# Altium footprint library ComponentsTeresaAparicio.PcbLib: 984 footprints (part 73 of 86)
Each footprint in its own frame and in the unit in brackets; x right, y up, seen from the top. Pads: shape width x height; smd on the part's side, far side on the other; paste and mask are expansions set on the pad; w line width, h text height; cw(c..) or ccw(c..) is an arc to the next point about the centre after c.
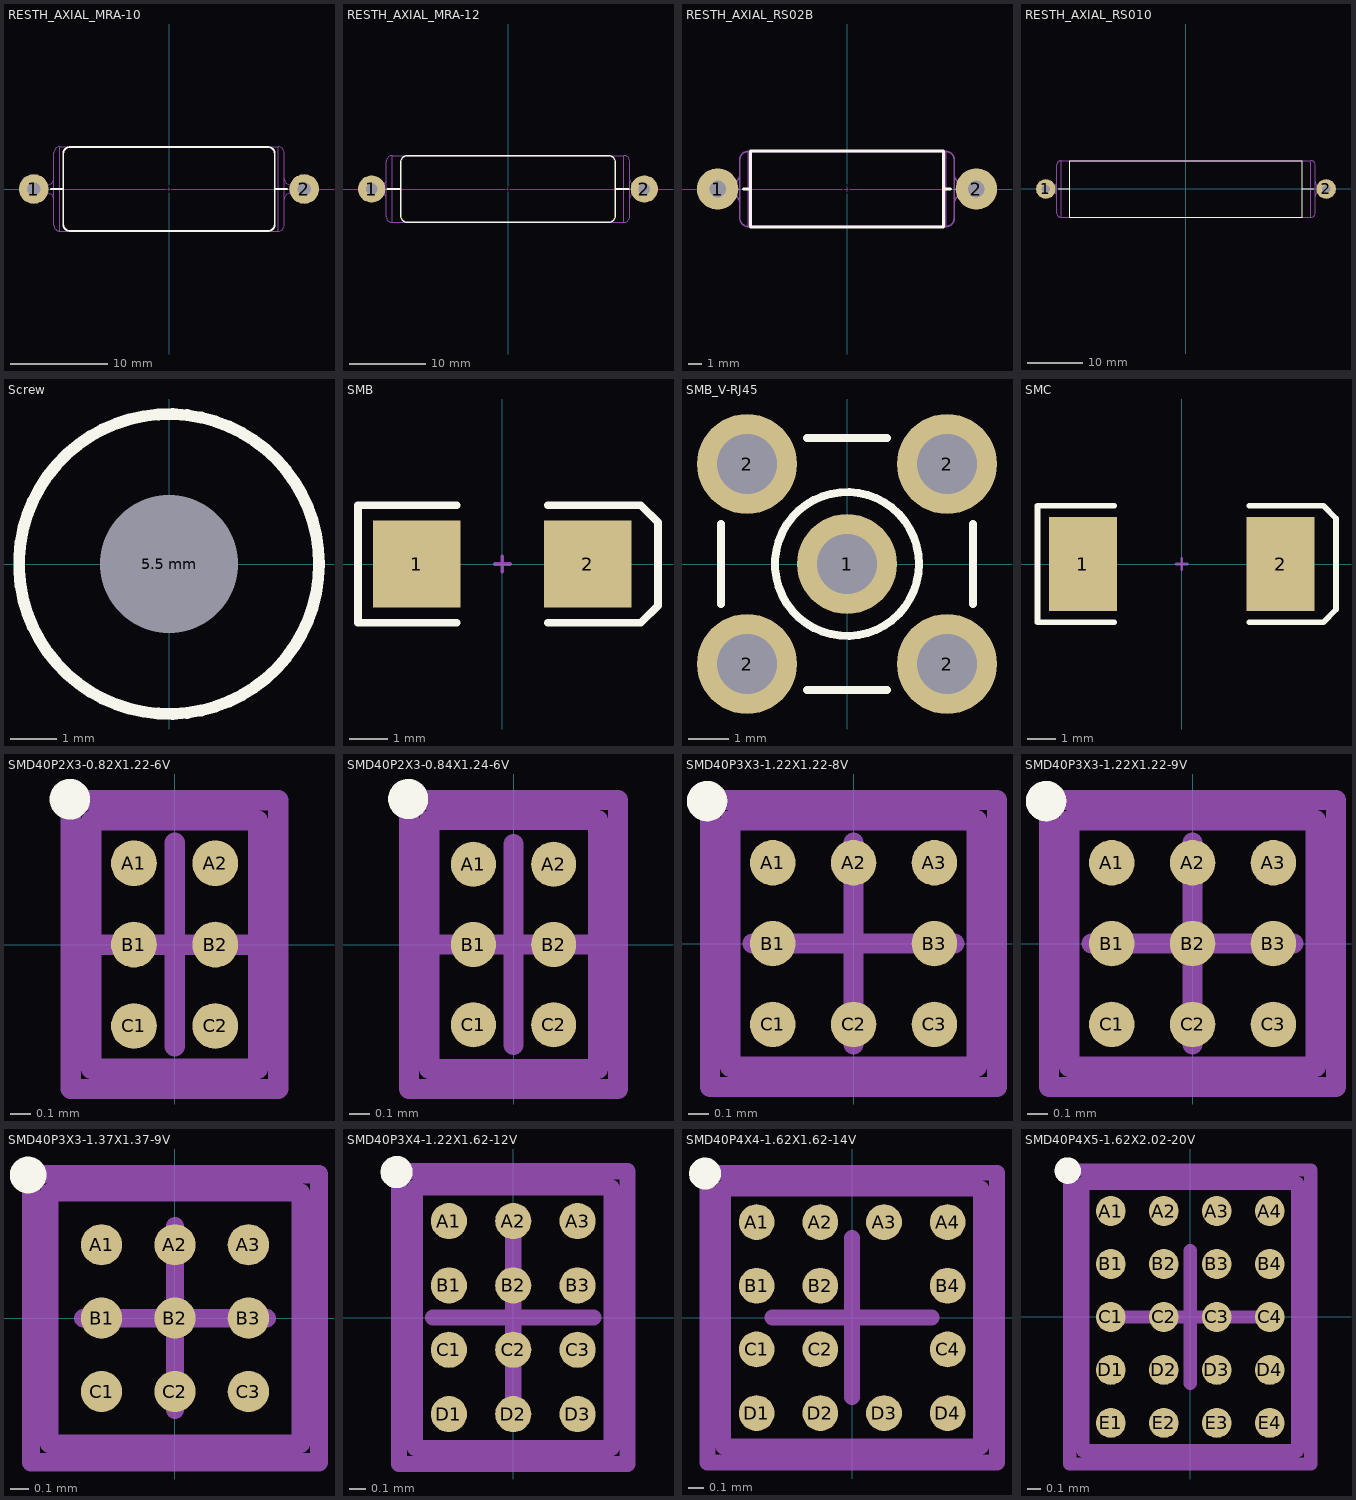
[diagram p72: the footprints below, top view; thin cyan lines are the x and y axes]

## RESTH_AXIAL_MRA-10 [mil] "MRA-10 Axial Resistor Thru-Hole; 2 Leads"
height 343
pads (3):
  round 50 on Mech14: 0(0,0)
  round 120 hole 54: 1(-550,0) 2(550,0)
Top Overlay:
  lines w7.87: -480,0 -430,0 ; 430,0 480,0 ; -430,-145 ccw(c-405,-145) -405,-170 405,-170 ccw(c405,-145) 430,-145 430,145 ccw(c405,145) 405,170 -405,170 ccw(c-405,145) -430,145 -430,-145
Mechanical 13:
  lines w5: -516,-17 -516,17 ; -493.5,-16.89 -493.5,17 ; -468.5,-42 ccw(c-493.5,-42) -493.5,-17 -550,-17 cw(c-550,0) -550,17 -493.5,17 ; -468.5,42 cw(c-493.5,42) -493.5,17 ; 468.5,-42 cw(c493.5,-42) 493.5,-17 ; 468.5,42 ccw(c493.5,42) 493.5,17 550,17 cw(c550,0) 550,-17 493.5,-17 ; 493.5,16.89 493.5,-17 ; 516,-17 516,17 ; -443.5,-171.5 cw(c-443.5,-146.5) -468.5,-146.5 -468.5,146.5 cw(c-443.5,146.5) -443.5,171.5 ; -443.5,-171.5 -443.5,171.5 ; -443.5,-171.5 443.5,-171.5 ; -443.5,171.5 443.5,171.5 ; 443.5,-171.5 ccw(c443.5,-146.5) 468.5,-146.5 468.5,146.5 ccw(c443.5,146.5) 443.5,171.5 ; 443.5,-171.5 443.5,171.5
3D body: height 341.65, standoff -100, extent -566.99,-171.16 567,171.17

## RESTH_AXIAL_MRA-12 [mil] "MRA-12 Axial Resistor Thru-Hole; 2 Leads"
height 343
pads (3):
  round 50 on Mech14: 0(0,0)
  round 140 hole 60: 1(-700,0) 2(700,0)
Top Overlay:
  lines w7.87: -620,0 -550,0 ; 550,0 620,0 ; -550,-139.99 ccw(c-520,-139.99) -520,-169.99 520,-170 ccw(c519.99,-139.99) 549.99,-139.99 550,140 ccw(c519.99,140) 519.99,170 -520,170 ccw(c-520,140) -550,140 -550,-140
Mechanical 13:
  lines w5: -666,-17 -666,17 ; -625,-47 ccw(c-655,-47) -655,-17 ; -625,47 cw(c-655,47) -655,17 ; 625,-47 cw(c655,-47) 655,-17 ; 625,47 ccw(c655,47) 655,17 ; 666,-17 666,17 ; -655,-17 -655,17 ; -655,-17 -700,-17 cw(c-700,0) -700,17 -655,17 ; -595,-171.5 cw(c-595,-141.5) -625,-141.5 -625,141.5 cw(c-595,141.5) -595,171.5 ; -595,-171.5 -595,171.5 ; -595,-171.5 595,-171.5 ; -595,171.5 595,171.5 ; 595,-171.5 ccw(c595,-141.5) 625,-141.5 625,141.5 ccw(c595,141.5) 595,171.5 ; 595,-171.5 595,171.5 ; 655,-17 655,17 ; 655,-17 700,-17 ccw(c700,0) 700,17 655,17
3D body: height 341.65, standoff -100, extent -717,-171.15 717,171.17

## RESTH_AXIAL_RS02B [mil] "Axial Resistor Thru-Hole; 2 Leads"
height 218
pads (3):
  round 50 on Mech14: 0(0,0)
  round 120 hole 48: 1(-375,0) 2(375,0)
Top Overlay:
  lines w7.87: -300,0 -280,0 ; 280,0 300,0 ; -280,-110 280,-110 280,110 -280,110 -280,-110
Mechanical 13:
  lines w5: -341,-17 -341,17 ; -311,-42 ccw(c-336,-42) -336,-17 ; -311,42 cw(c-336,42) -336,17 ; 311,-42 cw(c336,-42) 336,-17 ; 311,42 ccw(c336,42) 336,17 ; 341,-17 341,17 ; -336,-17 -336,17 ; -336,-17 -375,-17 cw(c-375,0) -375,17 -336,17 ; -286,-109 cw(c-286,-84) -311,-84 -311,84 cw(c-286,84) -286,109 ; -286,-109 -286,109 ; -286,-109 286,-109 ; -286,109 286,109 ; 286,-109 ccw(c286,-84) 311,-84 311,84 ccw(c286,84) 286,109 ; 286,-109 286,109 ; 336,-17 336,17 ; 336,-17 375,-17 ccw(c375,0) 375,17 336,17
3D body: height 217.14, standoff -100, extent -392,-108.78 392,108.79

## RESTH_AXIAL_RS010 [mil] "Axial Resistor Thru-Hole; 2 Leads"
height 406
pads (3):
  round 50 on Mech14: 0(0,0)
  round 140 hole 60: 1(-1000,0) 2(1000,0)
Top Overlay:
  lines w7.87: -910,0 -830,0 ; 830,0 910,0 ; -830,-200 -830,200 830,200 830,-200 -830,-200
Mechanical 13:
  lines w5: -958,-21 -958,21 ; -921,-51 ccw(c-951,-51) -951,-21 ; -921,51 cw(c-951,51) -951,21 ; 921,-51 cw(c951,-51) 951,-21 ; 921,51 ccw(c951,51) 951,21 ; 958,-21 958,21 ; -951,-21 -1000,-21 cw(c-1000,0) -1000,21 -951,21 ; -951,-21 -951,21 ; -891,-203 cw(c-891,-173) -921,-173 -921,173 cw(c-891,173) -891,203 ; -891,-203 891,-203 ; -891,-203 -891,203 ; -891,203 891,203 ; 891,-203 ccw(c891,-173) 921,-173 921,173 ccw(c891,173) 891,203 ; 891,-203 891,203 ; 951,-21 1000,-21 ccw(c1000,0) 1000,21 951,21 ; 951,-21 951,21
3D body: height 404.4, standoff -100, extent -1020.99,-202.59 1021,202.61

## Screw [mil]
pads (1):
  round 60 hole 118.11: "5.5 mm"(0,0)
Top Overlay:
  circle w10: c0,0 r128.06
3D body: height 318.11, standoff -429.92, extent -110,-110 106.54,106.54

## SMB [mm] "DO-214-AA/SMB; 2 C-Bend Leads; Body 5.3 x 3.6 mm, inc. leads (LxW)"
height 2.54
pads (2):
  rect 2.3x2.3 smd: 1(-2.25,0) 2(2.25,0)
Top Overlay:
  lines w0.2: -1.2,-1.55 -3.8,-1.55 -3.8,1.55 -1.2,1.55 ; 1.2,-1.55 3.65,-1.55 4.1,-1.1 4.1,1.1 3.65,1.55 1.2,1.55
Mechanical 1:
  lines w0.1: -0.2,0 0.2,0 ; 0,-0.2 0,0.2

## SMB_V-RJ45 [mm] "Connector; SMB Straight"
pads (5):
  round 2.5 hole 1.5: 1(0,0) 2(-2.5,-2.5) 2(-2.5,2.5) 2(2.5,-2.5) 2(2.5,2.5)
Top Overlay:
  circle w0.2: c0,0 r1.8
  lines w0.2: -3.15,-1 -3.15,1 ; -1,-3.15 1,-3.15 ; -1,3.15 1,3.15 ; 3.15,-1 3.15,1
Mechanical 1:
  circle w0.025: c0,0 r0.2
  circle w0.025: c0,0 r1.05
  circle w0.025: c0,0 r1.8

## SMC [mm] "DO-214-AB/SMC; 2 C-Bend Leads; Body 7.9 x 5.9 mm, inc. leads (LxW)"
height 2.65
pads (2):
  rect 2.4x3.3 smd: 1(-3.475,0) 2(3.475,0)
Top Overlay:
  lines w0.2: -2.375,-2.05 -5.075,-2.05 -5.075,2.05 -2.375,2.05 ; 2.375,-2.05 4.975,-2.05 5.425,-1.6 5.425,1.6 4.975,2.055 ; 2.375,2.05 4.975,2.05
Mechanical 1:
  lines w0.1: -0.2,0 0.2,0 ; 0,-0.2 0,0.2

## SMD40P2X3-0.82X1.22-6V [mm] "Micro SMD, 6-Leads, Body 1.22x0.82mm, Pitch 0.4mm, NSC Recommended"
height 0.68
pads (6):
  round 0.225 smd paste-0.112 mask+0.05: A1(-0.2,0.4) A2(0.2,0.4) B1(-0.2,0) B2(0.2,0) C1(-0.2,-0.4) C2(0.2,-0.4)
Top Overlay:
  circle w0.1: c-0.515,0.715 r0.05
Top Paste:
  circle w0.05: c0.3,-0.5 r0.025
  circle w0.05: c0.15,-0.35 r0.025
  circle w0.05: c0.15,-0.5 r0.025
  circle w0.05: c0.3,-0.35 r0.025
  circle w0.05: c-0.15,-0.5 r0.025
  circle w0.05: c-0.3,-0.35 r0.025
  circle w0.05: c-0.3,-0.5 r0.025
  circle w0.05: c-0.15,-0.35 r0.025
  circle w0.05: c0.3,-0.075 r0.025
  circle w0.05: c0.15,0.075 r0.025
  circle w0.05: c0.15,-0.075 r0.025
  circle w0.05: c0.3,0.075 r0.025
  circle w0.05: c-0.15,-0.075 r0.025
  circle w0.05: c-0.3,0.075 r0.025
  circle w0.05: c-0.3,-0.075 r0.025
  circle w0.05: c-0.15,0.075 r0.025
  circle w0.05: c0.3,0.35 r0.025
  circle w0.05: c0.15,0.5 r0.025
  circle w0.05: c0.15,0.35 r0.025
  circle w0.05: c0.3,0.5 r0.025
  circle w0.05: c-0.15,0.35 r0.025
  circle w0.05: c-0.3,0.5 r0.025
  circle w0.05: c-0.3,0.35 r0.025
  circle w0.05: c-0.15,0.5 r0.025
  region: 0.15,-0.35 0.15,-0.5 0.3,-0.5 0.3,-0.35
  region: 0.35,-0.5 0.35,-0.35 0.3,-0.35 0.3,-0.5
  region: 0.3,-0.3 0.15,-0.3 0.15,-0.35 0.3,-0.35
  region: 0.1,-0.35 0.1,-0.5 0.15,-0.5 0.15,-0.35
  rectangle: 0.15,-0.55 0.3,-0.5
  region: -0.3,-0.35 -0.3,-0.5 -0.15,-0.5 -0.15,-0.35
  region: -0.1,-0.5 -0.1,-0.35 -0.15,-0.35 -0.15,-0.5
  region: -0.15,-0.3 -0.3,-0.3 -0.3,-0.35 -0.15,-0.35
  region: -0.35,-0.35 -0.35,-0.5 -0.3,-0.5 -0.3,-0.35
  rectangle: -0.3,-0.55 -0.15,-0.5
  region: 0.15,0.075 0.15,-0.075 0.3,-0.075 0.3,0.075
  region: 0.35,-0.075 0.35,0.075 0.3,0.075 0.3,-0.075
  region: 0.3,0.125 0.15,0.125 0.15,0.075 0.3,0.075
  region: 0.1,0.075 0.1,-0.075 0.15,-0.075 0.15,0.075
  rectangle: 0.15,-0.125 0.3,-0.075
  region: -0.3,0.075 -0.3,-0.075 -0.15,-0.075 -0.15,0.075
  region: -0.1,-0.075 -0.1,0.075 -0.15,0.075 -0.15,-0.075
  region: -0.15,0.125 -0.3,0.125 -0.3,0.075 -0.15,0.075
  region: -0.35,0.075 -0.35,-0.075 -0.3,-0.075 -0.3,0.075
  rectangle: -0.3,-0.125 -0.15,-0.075
  region: 0.15,0.5 0.15,0.35 0.3,0.35 0.3,0.5
  region: 0.35,0.35 0.35,0.5 0.3,0.5 0.3,0.35
  region: 0.3,0.55 0.15,0.55 0.15,0.5 0.3,0.5
  region: 0.1,0.5 0.1,0.35 0.15,0.35 0.15,0.5
  rectangle: 0.15,0.3 0.3,0.35
  region: -0.3,0.5 -0.3,0.35 -0.15,0.35 -0.15,0.5
  region: -0.1,0.35 -0.1,0.5 -0.15,0.5 -0.15,0.35
  region: -0.15,0.55 -0.3,0.55 -0.3,0.5 -0.15,0.5
  region: -0.35,0.5 -0.35,0.35 -0.3,0.35 -0.3,0.5
  rectangle: -0.3,0.3 -0.15,0.35
Mechanical 13:
  lines w0.1: -0.41,-0.61 0.41,-0.61 0.41,0.61 -0.41,0.61 -0.41,-0.61
Mechanical 15:
  lines w0.1: -0.5,0 0.5,0 ; 0,-0.5 0,0.5 ; -0.51,-0.71 0.51,-0.71 0.51,0.71 -0.51,0.71 -0.51,-0.71
3D body: height 0.68, standoff 0, extent -0.41,-0.61 0.41,0.61

## SMD40P2X3-0.84X1.24-6V [mm] "Micro SMD, 6-Leads, Body 1.24x0.84mm, Pitch 0.4mm, NSC Recommended"
height 0.68
pads (6):
  round 0.225 smd paste-0.112 mask+0.05: A1(-0.2,0.4) A2(0.2,0.4) B1(-0.2,0) B2(0.2,0) C1(-0.2,-0.4) C2(0.2,-0.4)
Top Overlay:
  circle w0.1: c-0.525,0.725 r0.05
Top Paste:
  circle w0.05: c0.15,0.075 r0.025
  circle w0.05: c0.3,-0.075 r0.025
  circle w0.05: c0.15,-0.075 r0.025
  circle w0.05: c0.3,0.075 r0.025
  circle w0.05: c0.15,0.35 r0.025
  circle w0.05: c0.3,0.5 r0.025
  circle w0.05: c0.3,0.35 r0.025
  circle w0.05: c0.15,0.5 r0.025
  circle w0.05: c0.15,-0.35 r0.025
  circle w0.05: c0.3,-0.5 r0.025
  circle w0.05: c0.3,-0.35 r0.025
  circle w0.05: c0.15,-0.5 r0.025
  circle w0.05: c-0.15,0.075 r0.025
  circle w0.05: c-0.3,-0.075 r0.025
  circle w0.05: c-0.15,-0.075 r0.025
  circle w0.05: c-0.3,0.075 r0.025
  circle w0.05: c-0.15,0.35 r0.025
  circle w0.05: c-0.3,0.5 r0.025
  circle w0.05: c-0.3,0.35 r0.025
  circle w0.05: c-0.15,0.5 r0.025
  circle w0.05: c-0.15,-0.35 r0.025
  circle w0.05: c-0.3,-0.5 r0.025
  circle w0.05: c-0.3,-0.35 r0.025
  circle w0.05: c-0.15,-0.5 r0.025
  region: 0.3,0.075 0.15,0.075 0.15,-0.075 0.3,-0.075
  rectangle: 0.15,0.075 0.3,0.125
  region: 0.3,0.075 0.3,-0.075 0.35,-0.075 0.35,0.075
  region: 0.3,-0.075 0.15,-0.075 0.15,-0.125 0.3,-0.125
  region: 0.15,-0.075 0.15,0.075 0.1,0.075 0.1,-0.075
  region: 0.15,0.5 0.15,0.35 0.3,0.35 0.3,0.5
  region: 0.15,0.35 0.15,0.5 0.1,0.5 0.1,0.35
  rectangle: 0.15,0.5 0.3,0.55
  region: 0.3,0.5 0.3,0.35 0.35,0.35 0.35,0.5
  region: 0.3,0.35 0.15,0.35 0.15,0.3 0.3,0.3
  region: 0.3,-0.5 0.3,-0.35 0.15,-0.35 0.15,-0.5
  region: 0.1,-0.35 0.1,-0.5 0.15,-0.5 0.15,-0.35
  rectangle: 0.15,-0.55 0.3,-0.5
  region: 0.35,-0.5 0.35,-0.35 0.3,-0.35 0.3,-0.5
  region: 0.3,-0.3 0.15,-0.3 0.15,-0.35 0.3,-0.35
  rectangle: -0.3,-0.075 -0.15,0.075
  region: -0.15,0.125 -0.3,0.125 -0.3,0.075 -0.15,0.075
  region: -0.35,0.075 -0.35,-0.075 -0.3,-0.075 -0.3,0.075
  rectangle: -0.3,-0.125 -0.15,-0.075
  region: -0.1,-0.075 -0.1,0.075 -0.15,0.075 -0.15,-0.075
  region: -0.3,0.5 -0.3,0.35 -0.15,0.35 -0.15,0.5
  region: -0.1,0.35 -0.1,0.5 -0.15,0.5 -0.15,0.35
  region: -0.15,0.55 -0.3,0.55 -0.3,0.5 -0.15,0.5
  region: -0.35,0.5 -0.35,0.35 -0.3,0.35 -0.3,0.5
  rectangle: -0.3,0.3 -0.15,0.35
  region: -0.15,-0.5 -0.15,-0.35 -0.3,-0.35 -0.3,-0.5
  region: -0.15,-0.35 -0.15,-0.5 -0.1,-0.5 -0.1,-0.35
  region: -0.15,-0.5 -0.3,-0.5 -0.3,-0.55 -0.15,-0.55
  region: -0.3,-0.5 -0.3,-0.35 -0.35,-0.35 -0.35,-0.5
  rectangle: -0.3,-0.35 -0.15,-0.3
Mechanical 13:
  lines w0.1: -0.42,-0.62 0.42,-0.62 0.42,0.62 -0.42,0.62 -0.42,-0.62
Mechanical 15:
  lines w0.1: -0.5,0 0.5,0 ; 0,-0.5 0,0.5 ; -0.52,-0.72 0.52,-0.72 0.52,0.72 -0.52,0.72 -0.52,-0.72
3D body: height 0.68, standoff 0.17, extent -0.419,-0.619 0.419,0.619

## SMD40P3X3-1.22X1.22-8V [mm] "Micro SMD, 8-Leads, Body 1.22x1.22mm, Pitch 0.4mm, NSC Recommended"
height 0.68
pads (8):
  round 0.225 smd paste-0.112 mask+0.05: A1(-0.4,0.4) A2(0,0.4) A3(0.4,0.4) B1(-0.4,0) B3(0.4,0) C1(-0.4,-0.4) C2(0,-0.4) C3(0.4,-0.4)
Top Overlay:
  circle w0.1: c-0.725,0.705 r0.05
Top Paste:
  circle w0.05: c0.35,-0.075 r0.025
  circle w0.05: c0.5,0.075 r0.025
  circle w0.05: c0.35,0.075 r0.025
  circle w0.05: c0.5,-0.075 r0.025
  circle w0.05: c-0.075,-0.35 r0.025
  circle w0.05: c0.075,-0.5 r0.025
  circle w0.05: c0.075,-0.35 r0.025
  circle w0.05: c-0.075,-0.5 r0.025
  circle w0.05: c-0.35,0.075 r0.025
  circle w0.05: c-0.5,-0.075 r0.025
  circle w0.05: c-0.35,-0.075 r0.025
  circle w0.05: c-0.5,0.075 r0.025
  circle w0.05: c0.075,0.35 r0.025
  circle w0.05: c-0.075,0.5 r0.025
  circle w0.05: c-0.075,0.35 r0.025
  circle w0.05: c0.075,0.5 r0.025
  circle w0.05: c-0.35,0.35 r0.025
  circle w0.05: c-0.5,0.5 r0.025
  circle w0.05: c-0.5,0.35 r0.025
  circle w0.05: c-0.35,0.5 r0.025
  circle w0.05: c0.35,0.35 r0.025
  circle w0.05: c0.5,0.5 r0.025
  circle w0.05: c0.5,0.35 r0.025
  circle w0.05: c0.35,0.5 r0.025
  circle w0.05: c0.35,-0.35 r0.025
  circle w0.05: c0.5,-0.5 r0.025
  circle w0.05: c0.5,-0.35 r0.025
  circle w0.05: c0.35,-0.5 r0.025
  circle w0.05: c-0.35,-0.35 r0.025
  circle w0.05: c-0.5,-0.5 r0.025
  circle w0.05: c-0.5,-0.35 r0.025
  circle w0.05: c-0.35,-0.5 r0.025
  region: 0.5,0.075 0.35,0.075 0.35,-0.075 0.5,-0.075
  rectangle: 0.35,-0.125 0.5,-0.075
  region: 0.55,-0.075 0.55,0.075 0.5,0.075 0.5,-0.075
  region: 0.5,0.125 0.35,0.125 0.35,0.075 0.5,0.075
  region: 0.3,0.075 0.3,-0.075 0.35,-0.075 0.35,0.075
  region: 0.075,-0.5 0.075,-0.35 -0.075,-0.35 -0.075,-0.5
  region: -0.125,-0.35 -0.125,-0.5 -0.075,-0.5 -0.075,-0.35
  rectangle: -0.075,-0.55 0.075,-0.5
  region: 0.125,-0.5 0.125,-0.35 0.075,-0.35 0.075,-0.5
  region: 0.075,-0.3 -0.075,-0.3 -0.075,-0.35 0.075,-0.35
  rectangle: -0.5,-0.075 -0.35,0.075
  region: -0.35,0.125 -0.5,0.125 -0.5,0.075 -0.35,0.075
  region: -0.55,0.075 -0.55,-0.075 -0.5,-0.075 -0.5,0.075
  rectangle: -0.5,-0.125 -0.35,-0.075
  region: -0.3,-0.075 -0.3,0.075 -0.35,0.075 -0.35,-0.075
  region: -0.075,0.5 -0.075,0.35 0.075,0.35 0.075,0.5
  region: 0.125,0.35 0.125,0.5 0.075,0.5 0.075,0.35
  region: 0.075,0.55 -0.075,0.55 -0.075,0.5 0.075,0.5
  region: -0.125,0.5 -0.125,0.35 -0.075,0.35 -0.075,0.5
  rectangle: -0.075,0.3 0.075,0.35
  region: -0.5,0.5 -0.5,0.35 -0.35,0.35 -0.35,0.5
  region: -0.3,0.35 -0.3,0.5 -0.35,0.5 -0.35,0.35
  region: -0.35,0.55 -0.5,0.55 -0.5,0.5 -0.35,0.5
  region: -0.55,0.5 -0.55,0.35 -0.5,0.35 -0.5,0.5
  rectangle: -0.5,0.3 -0.35,0.35
  region: 0.35,0.5 0.35,0.35 0.5,0.35 0.5,0.5
  region: 0.35,0.35 0.35,0.5 0.3,0.5 0.3,0.35
  rectangle: 0.35,0.5 0.5,0.55
  region: 0.5,0.5 0.5,0.35 0.55,0.35 0.55,0.5
  region: 0.5,0.35 0.35,0.35 0.35,0.3 0.5,0.3
  region: 0.5,-0.5 0.5,-0.35 0.35,-0.35 0.35,-0.5
  region: 0.3,-0.35 0.3,-0.5 0.35,-0.5 0.35,-0.35
  rectangle: 0.35,-0.55 0.5,-0.5
  region: 0.55,-0.5 0.55,-0.35 0.5,-0.35 0.5,-0.5
  region: 0.5,-0.3 0.35,-0.3 0.35,-0.35 0.5,-0.35
  region: -0.35,-0.5 -0.35,-0.35 -0.5,-0.35 -0.5,-0.5
  region: -0.35,-0.35 -0.35,-0.5 -0.3,-0.5 -0.3,-0.35
  region: -0.35,-0.5 -0.5,-0.5 -0.5,-0.55 -0.35,-0.55
  region: -0.5,-0.5 -0.5,-0.35 -0.55,-0.35 -0.55,-0.5
  rectangle: -0.5,-0.35 -0.35,-0.3
Mechanical 13:
  lines w0.1: -0.61,-0.61 0.61,-0.61 0.61,0.61 -0.61,0.61 -0.61,-0.61
Mechanical 15:
  lines w0.1: -0.5,0 0.5,0 ; 0,-0.5 0,0.5 ; -0.71,-0.71 0.71,-0.71 0.71,0.71 -0.71,0.71 -0.71,-0.71
3D body: height 0.68, standoff 0.17, extent -0.609,-0.609 0.609,0.609

## SMD40P3X3-1.22X1.22-9V [mm] "Micro SMD, 9-Leads, Body 1.22x1.22mm, Pitch 0.4mm, NSC Recommended"
height 0.68
pads (9):
  round 0.225 smd paste-0.112 mask+0.05: A1(-0.4,0.4) A2(0,0.4) A3(0.4,0.4) B1(-0.4,0) B2(0,0) B3(0.4,0) C1(-0.4,-0.4) C2(0,-0.4) C3(0.4,-0.4)
Top Overlay:
  circle w0.1: c-0.725,0.705 r0.05
Top Paste:
  circle w0.05: c0.075,-0.075 r0.025
  circle w0.05: c-0.075,0.075 r0.025
  circle w0.05: c-0.075,-0.075 r0.025
  circle w0.05: c0.075,0.075 r0.025
  circle w0.05: c-0.35,-0.5 r0.025
  circle w0.05: c-0.5,-0.35 r0.025
  circle w0.05: c-0.5,-0.5 r0.025
  circle w0.05: c-0.35,-0.35 r0.025
  circle w0.05: c0.35,-0.5 r0.025
  circle w0.05: c0.5,-0.35 r0.025
  circle w0.05: c0.5,-0.5 r0.025
  circle w0.05: c0.35,-0.35 r0.025
  circle w0.05: c0.35,0.5 r0.025
  circle w0.05: c0.5,0.35 r0.025
  circle w0.05: c0.5,0.5 r0.025
  circle w0.05: c0.35,0.35 r0.025
  circle w0.05: c-0.35,0.5 r0.025
  circle w0.05: c-0.5,0.35 r0.025
  circle w0.05: c-0.5,0.5 r0.025
  circle w0.05: c-0.35,0.35 r0.025
  circle w0.05: c0.075,0.5 r0.025
  circle w0.05: c-0.075,0.35 r0.025
  circle w0.05: c-0.075,0.5 r0.025
  circle w0.05: c0.075,0.35 r0.025
  circle w0.05: c-0.5,0.075 r0.025
  circle w0.05: c-0.35,-0.075 r0.025
  circle w0.05: c-0.5,-0.075 r0.025
  circle w0.05: c-0.35,0.075 r0.025
  circle w0.05: c-0.075,-0.5 r0.025
  circle w0.05: c0.075,-0.35 r0.025
  circle w0.05: c0.075,-0.5 r0.025
  circle w0.05: c-0.075,-0.35 r0.025
  circle w0.05: c0.5,-0.075 r0.025
  circle w0.05: c0.35,0.075 r0.025
  circle w0.05: c0.5,0.075 r0.025
  circle w0.05: c0.35,-0.075 r0.025
  region: -0.075,0.075 -0.075,-0.075 0.075,-0.075 0.075,0.075
  region: 0.125,-0.075 0.125,0.075 0.075,0.075 0.075,-0.075
  region: 0.075,0.125 -0.075,0.125 -0.075,0.075 0.075,0.075
  region: -0.125,0.075 -0.125,-0.075 -0.075,-0.075 -0.075,0.075
  rectangle: -0.075,-0.125 0.075,-0.075
  rectangle: -0.5,-0.35 -0.35,-0.3
  region: -0.5,-0.5 -0.5,-0.35 -0.55,-0.35 -0.55,-0.5
  region: -0.35,-0.5 -0.5,-0.5 -0.5,-0.55 -0.35,-0.55
  region: -0.35,-0.35 -0.35,-0.5 -0.3,-0.5 -0.3,-0.35
  region: -0.35,-0.5 -0.35,-0.35 -0.5,-0.35 -0.5,-0.5
  region: 0.5,-0.3 0.35,-0.3 0.35,-0.35 0.5,-0.35
  region: 0.55,-0.5 0.55,-0.35 0.5,-0.35 0.5,-0.5
  rectangle: 0.35,-0.55 0.5,-0.5
  region: 0.3,-0.35 0.3,-0.5 0.35,-0.5 0.35,-0.35
  region: 0.5,-0.5 0.5,-0.35 0.35,-0.35 0.35,-0.5
  region: 0.5,0.35 0.35,0.35 0.35,0.3 0.5,0.3
  region: 0.5,0.5 0.5,0.35 0.55,0.35 0.55,0.5
  rectangle: 0.35,0.5 0.5,0.55
  region: 0.35,0.35 0.35,0.5 0.3,0.5 0.3,0.35
  region: 0.35,0.5 0.35,0.35 0.5,0.35 0.5,0.5
  rectangle: -0.5,0.3 -0.35,0.35
  region: -0.55,0.5 -0.55,0.35 -0.5,0.35 -0.5,0.5
  region: -0.35,0.55 -0.5,0.55 -0.5,0.5 -0.35,0.5
  region: -0.3,0.35 -0.3,0.5 -0.35,0.5 -0.35,0.35
  region: -0.5,0.5 -0.5,0.35 -0.35,0.35 -0.35,0.5
  rectangle: -0.075,0.3 0.075,0.35
  region: -0.125,0.5 -0.125,0.35 -0.075,0.35 -0.075,0.5
  region: 0.075,0.55 -0.075,0.55 -0.075,0.5 0.075,0.5
  region: 0.125,0.35 0.125,0.5 0.075,0.5 0.075,0.35
  region: -0.075,0.5 -0.075,0.35 0.075,0.35 0.075,0.5
  region: -0.3,-0.075 -0.3,0.075 -0.35,0.075 -0.35,-0.075
  rectangle: -0.5,-0.125 -0.35,-0.075
  region: -0.55,0.075 -0.55,-0.075 -0.5,-0.075 -0.5,0.075
  region: -0.35,0.125 -0.5,0.125 -0.5,0.075 -0.35,0.075
  rectangle: -0.5,-0.075 -0.35,0.075
  region: 0.075,-0.3 -0.075,-0.3 -0.075,-0.35 0.075,-0.35
  region: 0.125,-0.5 0.125,-0.35 0.075,-0.35 0.075,-0.5
  rectangle: -0.075,-0.55 0.075,-0.5
  region: -0.125,-0.35 -0.125,-0.5 -0.075,-0.5 -0.075,-0.35
  region: 0.075,-0.5 0.075,-0.35 -0.075,-0.35 -0.075,-0.5
  region: 0.3,0.075 0.3,-0.075 0.35,-0.075 0.35,0.075
  region: 0.5,0.125 0.35,0.125 0.35,0.075 0.5,0.075
  region: 0.55,-0.075 0.55,0.075 0.5,0.075 0.5,-0.075
  rectangle: 0.35,-0.125 0.5,-0.075
  region: 0.5,0.075 0.35,0.075 0.35,-0.075 0.5,-0.075
Mechanical 13:
  lines w0.1: -0.61,-0.61 0.61,-0.61 0.61,0.61 -0.61,0.61 -0.61,-0.61
Mechanical 15:
  lines w0.1: -0.5,0 0.5,0 ; 0,-0.5 0,0.5 ; -0.71,-0.71 0.71,-0.71 0.71,0.71 -0.71,0.71 -0.71,-0.71
3D body: height 0.68, standoff 0, extent -0.609,-0.609 0.609,0.609

## SMD40P3X3-1.37X1.37-9V [mm] "Micro SMD, 9-Leads, Body 1.37x1.37mm, Pitch 0.4mm, NSC Recommended"
height 0.68
pads (9):
  round 0.225 smd paste-0.112 mask+0.05: A1(-0.4,0.4) A2(0,0.4) A3(0.4,0.4) B1(-0.4,0) B2(0,0) B3(0.4,0) C1(-0.4,-0.4) C2(0,-0.4) C3(0.4,-0.4)
Top Overlay:
  circle w0.1: c-0.8,0.78 r0.05
Top Paste:
  circle w0.05: c-0.075,-0.35 r0.025
  circle w0.05: c0.075,-0.5 r0.025
  circle w0.05: c0.075,-0.35 r0.025
  circle w0.05: c-0.075,-0.5 r0.025
  circle w0.05: c-0.35,0.075 r0.025
  circle w0.05: c-0.5,-0.075 r0.025
  circle w0.05: c-0.35,-0.075 r0.025
  circle w0.05: c-0.5,0.075 r0.025
  circle w0.05: c0.075,0.35 r0.025
  circle w0.05: c-0.075,0.5 r0.025
  circle w0.05: c-0.075,0.35 r0.025
  circle w0.05: c0.075,0.5 r0.025
  circle w0.05: c0.35,-0.075 r0.025
  circle w0.05: c0.5,0.075 r0.025
  circle w0.05: c0.35,0.075 r0.025
  circle w0.05: c0.5,-0.075 r0.025
  circle w0.05: c-0.35,-0.5 r0.025
  circle w0.05: c-0.5,-0.35 r0.025
  circle w0.05: c-0.5,-0.5 r0.025
  circle w0.05: c-0.35,-0.35 r0.025
  circle w0.05: c0.35,-0.5 r0.025
  circle w0.05: c0.5,-0.35 r0.025
  circle w0.05: c0.5,-0.5 r0.025
  circle w0.05: c0.35,-0.35 r0.025
  circle w0.05: c0.35,0.5 r0.025
  circle w0.05: c0.5,0.35 r0.025
  circle w0.05: c0.5,0.5 r0.025
  circle w0.05: c0.35,0.35 r0.025
  circle w0.05: c-0.35,0.5 r0.025
  circle w0.05: c-0.5,0.35 r0.025
  circle w0.05: c-0.5,0.5 r0.025
  circle w0.05: c-0.35,0.35 r0.025
  circle w0.05: c0.075,0.075 r0.025
  circle w0.05: c-0.075,-0.075 r0.025
  circle w0.05: c-0.075,0.075 r0.025
  circle w0.05: c0.075,-0.075 r0.025
  region: 0.075,-0.5 0.075,-0.35 -0.075,-0.35 -0.075,-0.5
  region: -0.125,-0.35 -0.125,-0.5 -0.075,-0.5 -0.075,-0.35
  rectangle: -0.075,-0.55 0.075,-0.5
  region: 0.125,-0.5 0.125,-0.35 0.075,-0.35 0.075,-0.5
  region: 0.075,-0.3 -0.075,-0.3 -0.075,-0.35 0.075,-0.35
  rectangle: -0.5,-0.075 -0.35,0.075
  region: -0.35,0.125 -0.5,0.125 -0.5,0.075 -0.35,0.075
  region: -0.55,0.075 -0.55,-0.075 -0.5,-0.075 -0.5,0.075
  rectangle: -0.5,-0.125 -0.35,-0.075
  region: -0.3,-0.075 -0.3,0.075 -0.35,0.075 -0.35,-0.075
  region: -0.075,0.5 -0.075,0.35 0.075,0.35 0.075,0.5
  region: 0.125,0.35 0.125,0.5 0.075,0.5 0.075,0.35
  region: 0.075,0.55 -0.075,0.55 -0.075,0.5 0.075,0.5
  region: -0.125,0.5 -0.125,0.35 -0.075,0.35 -0.075,0.5
  rectangle: -0.075,0.3 0.075,0.35
  region: 0.5,0.075 0.35,0.075 0.35,-0.075 0.5,-0.075
  rectangle: 0.35,-0.125 0.5,-0.075
  region: 0.55,-0.075 0.55,0.075 0.5,0.075 0.5,-0.075
  region: 0.5,0.125 0.35,0.125 0.35,0.075 0.5,0.075
  region: 0.3,0.075 0.3,-0.075 0.35,-0.075 0.35,0.075
  rectangle: -0.5,-0.35 -0.35,-0.3
  region: -0.5,-0.5 -0.5,-0.35 -0.55,-0.35 -0.55,-0.5
  region: -0.35,-0.5 -0.5,-0.5 -0.5,-0.55 -0.35,-0.55
  region: -0.35,-0.35 -0.35,-0.5 -0.3,-0.5 -0.3,-0.35
  region: -0.35,-0.5 -0.35,-0.35 -0.5,-0.35 -0.5,-0.5
  region: 0.5,-0.3 0.35,-0.3 0.35,-0.35 0.5,-0.35
  region: 0.55,-0.5 0.55,-0.35 0.5,-0.35 0.5,-0.5
  rectangle: 0.35,-0.55 0.5,-0.5
  region: 0.3,-0.35 0.3,-0.5 0.35,-0.5 0.35,-0.35
  region: 0.5,-0.5 0.5,-0.35 0.35,-0.35 0.35,-0.5
  region: 0.5,0.35 0.35,0.35 0.35,0.3 0.5,0.3
  region: 0.5,0.5 0.5,0.35 0.55,0.35 0.55,0.5
  rectangle: 0.35,0.5 0.5,0.55
  region: 0.35,0.35 0.35,0.5 0.3,0.5 0.3,0.35
  region: 0.35,0.5 0.35,0.35 0.5,0.35 0.5,0.5
  rectangle: -0.5,0.3 -0.35,0.35
  region: -0.55,0.5 -0.55,0.35 -0.5,0.35 -0.5,0.5
  region: -0.35,0.55 -0.5,0.55 -0.5,0.5 -0.35,0.5
  region: -0.3,0.35 -0.3,0.5 -0.35,0.5 -0.35,0.35
  region: -0.5,0.5 -0.5,0.35 -0.35,0.35 -0.35,0.5
  rectangle: -0.075,-0.125 0.075,-0.075
  region: -0.125,0.075 -0.125,-0.075 -0.075,-0.075 -0.075,0.075
  region: 0.075,0.125 -0.075,0.125 -0.075,0.075 0.075,0.075
  region: 0.125,-0.075 0.125,0.075 0.075,0.075 0.075,-0.075
  region: -0.075,0.075 -0.075,-0.075 0.075,-0.075 0.075,0.075
Mechanical 13:
  lines w0.1: -0.685,-0.685 0.685,-0.685 0.685,0.685 -0.685,0.685 -0.685,-0.685
Mechanical 15:
  lines w0.1: -0.5,0 0.5,0 ; 0,-0.5 0,0.5 ; -0.785,-0.785 0.785,-0.785 0.785,0.785 -0.785,0.785 -0.785,-0.785
3D body: height 0.68, standoff 0, extent -0.684,-0.684 0.684,0.684

## SMD40P3X4-1.22X1.62-12V [mm] "Micro SMD, 12-Leads, Body 1.62x1.22mm, Pitch 0.4mm, NSC Recommended"
height 0.68
pads (12):
  round 0.225 smd paste-0.112 mask+0.05: A1(-0.4,0.6) A2(0,0.6) A3(0.4,0.6) B1(-0.4,0.2) B2(0,0.2) B3(0.4,0.2) C1(-0.4,-0.2) C2(0,-0.2) C3(0.4,-0.2) D1(-0.4,-0.6) D2(0,-0.6) D3(0.4,-0.6)
Top Overlay:
  circle w0.1: c-0.725,0.905 r0.05
Top Paste:
  circle w0.05: c0.075,-0.275 r0.025
  circle w0.05: c-0.075,-0.125 r0.025
  circle w0.05: c-0.075,-0.275 r0.025
  circle w0.05: c0.075,-0.125 r0.025
  circle w0.05: c0.075,0.125 r0.025
  circle w0.05: c-0.075,0.275 r0.025
  circle w0.05: c-0.075,0.125 r0.025
  circle w0.05: c0.075,0.275 r0.025
  circle w0.05: c-0.35,-0.125 r0.025
  circle w0.05: c-0.5,-0.275 r0.025
  circle w0.05: c-0.35,-0.275 r0.025
  circle w0.05: c-0.5,-0.125 r0.025
  circle w0.05: c-0.35,0.275 r0.025
  circle w0.05: c-0.5,0.125 r0.025
  circle w0.05: c-0.35,0.125 r0.025
  circle w0.05: c-0.5,0.275 r0.025
  circle w0.05: c0.075,0.55 r0.025
  circle w0.05: c-0.075,0.7 r0.025
  circle w0.05: c-0.075,0.55 r0.025
  circle w0.05: c0.075,0.7 r0.025
  circle w0.05: c0.35,0.125 r0.025
  circle w0.05: c0.5,0.275 r0.025
  circle w0.05: c0.35,0.275 r0.025
  circle w0.05: c0.5,0.125 r0.025
  circle w0.05: c0.35,-0.275 r0.025
  circle w0.05: c0.5,-0.125 r0.025
  circle w0.05: c0.35,-0.125 r0.025
  circle w0.05: c0.5,-0.275 r0.025
  circle w0.05: c-0.075,-0.55 r0.025
  circle w0.05: c0.075,-0.7 r0.025
  circle w0.05: c0.075,-0.55 r0.025
  circle w0.05: c-0.075,-0.7 r0.025
  circle w0.05: c-0.35,-0.55 r0.025
  circle w0.05: c-0.5,-0.7 r0.025
  circle w0.05: c-0.5,-0.55 r0.025
  circle w0.05: c-0.35,-0.7 r0.025
  circle w0.05: c-0.35,0.55 r0.025
  circle w0.05: c-0.5,0.7 r0.025
  circle w0.05: c-0.5,0.55 r0.025
  circle w0.05: c-0.35,0.7 r0.025
  circle w0.05: c0.35,0.55 r0.025
  circle w0.05: c0.5,0.7 r0.025
  circle w0.05: c0.5,0.55 r0.025
  circle w0.05: c0.35,0.7 r0.025
  circle w0.05: c0.35,-0.55 r0.025
  circle w0.05: c0.5,-0.7 r0.025
  circle w0.05: c0.5,-0.55 r0.025
  circle w0.05: c0.35,-0.7 r0.025
  region: -0.075,-0.125 -0.075,-0.275 0.075,-0.275 0.075,-0.125
  region: 0.125,-0.275 0.125,-0.125 0.075,-0.125 0.075,-0.275
  region: 0.075,-0.075 -0.075,-0.075 -0.075,-0.125 0.075,-0.125
  region: -0.125,-0.125 -0.125,-0.275 -0.075,-0.275 -0.075,-0.125
  rectangle: -0.075,-0.325 0.075,-0.275
  region: -0.075,0.275 -0.075,0.125 0.075,0.125 0.075,0.275
  region: 0.125,0.125 0.125,0.275 0.075,0.275 0.075,0.125
  region: 0.075,0.325 -0.075,0.325 -0.075,0.275 0.075,0.275
  region: -0.125,0.275 -0.125,0.125 -0.075,0.125 -0.075,0.275
  rectangle: -0.075,0.075 0.075,0.125
  rectangle: -0.5,-0.275 -0.35,-0.125
  region: -0.35,-0.075 -0.5,-0.075 -0.5,-0.125 -0.35,-0.125
  region: -0.55,-0.125 -0.55,-0.275 -0.5,-0.275 -0.5,-0.125
  rectangle: -0.5,-0.325 -0.35,-0.275
  region: -0.3,-0.275 -0.3,-0.125 -0.35,-0.125 -0.35,-0.275
  rectangle: -0.5,0.125 -0.35,0.275
  region: -0.35,0.325 -0.5,0.325 -0.5,0.275 -0.35,0.275
  region: -0.55,0.275 -0.55,0.125 -0.5,0.125 -0.5,0.275
  rectangle: -0.5,0.075 -0.35,0.125
  region: -0.3,0.125 -0.3,0.275 -0.35,0.275 -0.35,0.125
  region: -0.075,0.7 -0.075,0.55 0.075,0.55 0.075,0.7
  region: 0.125,0.55 0.125,0.7 0.075,0.7 0.075,0.55
  region: 0.075,0.75 -0.075,0.75 -0.075,0.7 0.075,0.7
  region: -0.125,0.7 -0.125,0.55 -0.075,0.55 -0.075,0.7
  rectangle: -0.075,0.5 0.075,0.55
  region: 0.5,0.275 0.35,0.275 0.35,0.125 0.5,0.125
  rectangle: 0.35,0.075 0.5,0.125
  region: 0.55,0.125 0.55,0.275 0.5,0.275 0.5,0.125
  region: 0.5,0.325 0.35,0.325 0.35,0.275 0.5,0.275
  region: 0.3,0.275 0.3,0.125 0.35,0.125 0.35,0.275
  region: 0.5,-0.125 0.35,-0.125 0.35,-0.275 0.5,-0.275
  rectangle: 0.35,-0.325 0.5,-0.275
  region: 0.55,-0.275 0.55,-0.125 0.5,-0.125 0.5,-0.275
  region: 0.5,-0.075 0.35,-0.075 0.35,-0.125 0.5,-0.125
  region: 0.3,-0.125 0.3,-0.275 0.35,-0.275 0.35,-0.125
  region: 0.075,-0.7 0.075,-0.55 -0.075,-0.55 -0.075,-0.7
  region: -0.125,-0.55 -0.125,-0.7 -0.075,-0.7 -0.075,-0.55
  rectangle: -0.075,-0.75 0.075,-0.7
  region: 0.125,-0.7 0.125,-0.55 0.075,-0.55 0.075,-0.7
  region: 0.075,-0.5 -0.075,-0.5 -0.075,-0.55 0.075,-0.55
  region: -0.35,-0.7 -0.35,-0.55 -0.5,-0.55 -0.5,-0.7
  region: -0.35,-0.55 -0.35,-0.7 -0.3,-0.7 -0.3,-0.55
  region: -0.35,-0.7 -0.5,-0.7 -0.5,-0.75 -0.35,-0.75
  region: -0.5,-0.7 -0.5,-0.55 -0.55,-0.55 -0.55,-0.7
  rectangle: -0.5,-0.55 -0.35,-0.5
  region: -0.5,0.7 -0.5,0.55 -0.35,0.55 -0.35,0.7
  region: -0.3,0.55 -0.3,0.7 -0.35,0.7 -0.35,0.55
  region: -0.35,0.75 -0.5,0.75 -0.5,0.7 -0.35,0.7
  region: -0.55,0.7 -0.55,0.55 -0.5,0.55 -0.5,0.7
  rectangle: -0.5,0.5 -0.35,0.55
  region: 0.35,0.7 0.35,0.55 0.5,0.55 0.5,0.7
  region: 0.35,0.55 0.35,0.7 0.3,0.7 0.3,0.55
  rectangle: 0.35,0.7 0.5,0.75
  region: 0.5,0.7 0.5,0.55 0.55,0.55 0.55,0.7
  region: 0.5,0.55 0.35,0.55 0.35,0.5 0.5,0.5
  region: 0.5,-0.7 0.5,-0.55 0.35,-0.55 0.35,-0.7
  region: 0.3,-0.55 0.3,-0.7 0.35,-0.7 0.35,-0.55
  rectangle: 0.35,-0.75 0.5,-0.7
  region: 0.55,-0.7 0.55,-0.55 0.5,-0.55 0.5,-0.7
  region: 0.5,-0.5 0.35,-0.5 0.35,-0.55 0.5,-0.55
Mechanical 13:
  lines w0.1: -0.61,-0.81 0.61,-0.81 0.61,0.81 -0.61,0.81 -0.61,-0.81
Mechanical 15:
  lines w0.1: -0.5,0 0.5,0 ; 0,-0.5 0,0.5 ; -0.71,-0.91 0.71,-0.91 0.71,0.91 -0.71,0.91 -0.71,-0.91
3D body: height 0.68, standoff 0, extent -0.609,-0.809 0.609,0.809

## SMD40P4X4-1.62X1.62-14V [mm] "Micro SMD, 14-Leads, Body 1.62x1.62mm, Pitch 0.4mm, NSC Recommended"
height 0.68
pads (14):
  round 0.225 smd paste-0.112 mask+0.05: A1(-0.6,0.6) A2(-0.2,0.6) A3(0.2,0.6) A4(0.6,0.6) B1(-0.6,0.2) B2(-0.2,0.2) B4(0.6,0.2) C1(-0.6,-0.2) C2(-0.2,-0.2) C4(0.6,-0.2) D1(-0.6,-0.6) D2(-0.2,-0.6) D3(0.2,-0.6) D4(0.6,-0.6)
Top Overlay:
  circle w0.1: c-0.925,0.905 r0.05
Top Paste:
  circle w0.05: c0.55,0.7 r0.025
  circle w0.05: c0.7,0.55 r0.025
  circle w0.05: c0.7,0.7 r0.025
  circle w0.05: c0.55,0.55 r0.025
  circle w0.05: c-0.55,0.7 r0.025
  circle w0.05: c-0.7,0.55 r0.025
  circle w0.05: c-0.7,0.7 r0.025
  circle w0.05: c-0.55,0.55 r0.025
  circle w0.05: c-0.55,-0.7 r0.025
  circle w0.05: c-0.7,-0.55 r0.025
  circle w0.05: c-0.7,-0.7 r0.025
  circle w0.05: c-0.55,-0.55 r0.025
  circle w0.05: c0.55,-0.7 r0.025
  circle w0.05: c0.7,-0.55 r0.025
  circle w0.05: c0.7,-0.7 r0.025
  circle w0.05: c0.55,-0.55 r0.025
  circle w0.05: c-0.7,0.275 r0.025
  circle w0.05: c-0.55,0.125 r0.025
  circle w0.05: c-0.7,0.125 r0.025
  circle w0.05: c-0.55,0.275 r0.025
  circle w0.05: c-0.7,-0.125 r0.025
  circle w0.05: c-0.55,-0.275 r0.025
  circle w0.05: c-0.7,-0.275 r0.025
  circle w0.05: c-0.55,-0.125 r0.025
  circle w0.05: c-0.275,-0.7 r0.025
  circle w0.05: c-0.125,-0.55 r0.025
  circle w0.05: c-0.125,-0.7 r0.025
  circle w0.05: c-0.275,-0.55 r0.025
  circle w0.05: c0.7,-0.275 r0.025
  circle w0.05: c0.55,-0.125 r0.025
  circle w0.05: c0.7,-0.125 r0.025
  circle w0.05: c0.55,-0.275 r0.025
  circle w0.05: c0.7,0.125 r0.025
  circle w0.05: c0.55,0.275 r0.025
  circle w0.05: c0.7,0.275 r0.025
  circle w0.05: c0.55,0.125 r0.025
  circle w0.05: c0.275,0.7 r0.025
  circle w0.05: c0.125,0.55 r0.025
  circle w0.05: c0.125,0.7 r0.025
  circle w0.05: c0.275,0.55 r0.025
  circle w0.05: c-0.125,0.7 r0.025
  circle w0.05: c-0.275,0.55 r0.025
  circle w0.05: c-0.275,0.7 r0.025
  circle w0.05: c-0.125,0.55 r0.025
  circle w0.05: c0.275,-0.7 r0.025
  circle w0.05: c0.125,-0.55 r0.025
  circle w0.05: c0.125,-0.7 r0.025
  circle w0.05: c0.275,-0.55 r0.025
  circle w0.05: c-0.125,0.275 r0.025
  circle w0.05: c-0.275,0.125 r0.025
  circle w0.05: c-0.275,0.275 r0.025
  circle w0.05: c-0.125,0.125 r0.025
  circle w0.05: c-0.125,-0.125 r0.025
  circle w0.05: c-0.275,-0.275 r0.025
  circle w0.05: c-0.275,-0.125 r0.025
  circle w0.05: c-0.125,-0.275 r0.025
  region: 0.7,0.55 0.55,0.55 0.55,0.5 0.7,0.5
  region: 0.7,0.7 0.7,0.55 0.75,0.55 0.75,0.7
  rectangle: 0.55,0.7 0.7,0.75
  region: 0.55,0.55 0.55,0.7 0.5,0.7 0.5,0.55
  region: 0.55,0.7 0.55,0.55 0.7,0.55 0.7,0.7
  rectangle: -0.7,0.5 -0.55,0.55
  region: -0.75,0.7 -0.75,0.55 -0.7,0.55 -0.7,0.7
  region: -0.55,0.75 -0.7,0.75 -0.7,0.7 -0.55,0.7
  region: -0.5,0.55 -0.5,0.7 -0.55,0.7 -0.55,0.55
  region: -0.7,0.7 -0.7,0.55 -0.55,0.55 -0.55,0.7
  rectangle: -0.7,-0.55 -0.55,-0.5
  region: -0.7,-0.7 -0.7,-0.55 -0.75,-0.55 -0.75,-0.7
  region: -0.55,-0.7 -0.7,-0.7 -0.7,-0.75 -0.55,-0.75
  region: -0.55,-0.55 -0.55,-0.7 -0.5,-0.7 -0.5,-0.55
  region: -0.55,-0.7 -0.55,-0.55 -0.7,-0.55 -0.7,-0.7
  region: 0.7,-0.5 0.55,-0.5 0.55,-0.55 0.7,-0.55
  region: 0.75,-0.7 0.75,-0.55 0.7,-0.55 0.7,-0.7
  rectangle: 0.55,-0.75 0.7,-0.7
  region: 0.5,-0.55 0.5,-0.7 0.55,-0.7 0.55,-0.55
  region: 0.7,-0.7 0.7,-0.55 0.55,-0.55 0.55,-0.7
  region: -0.5,0.125 -0.5,0.275 -0.55,0.275 -0.55,0.125
  rectangle: -0.7,0.075 -0.55,0.125
  region: -0.75,0.275 -0.75,0.125 -0.7,0.125 -0.7,0.275
  region: -0.55,0.325 -0.7,0.325 -0.7,0.275 -0.55,0.275
  rectangle: -0.7,0.125 -0.55,0.275
  region: -0.5,-0.275 -0.5,-0.125 -0.55,-0.125 -0.55,-0.275
  rectangle: -0.7,-0.325 -0.55,-0.275
  region: -0.75,-0.125 -0.75,-0.275 -0.7,-0.275 -0.7,-0.125
  region: -0.55,-0.075 -0.7,-0.075 -0.7,-0.125 -0.55,-0.125
  rectangle: -0.7,-0.275 -0.55,-0.125
  region: -0.125,-0.5 -0.275,-0.5 -0.275,-0.55 -0.125,-0.55
  region: -0.075,-0.7 -0.075,-0.55 -0.125,-0.55 -0.125,-0.7
  rectangle: -0.275,-0.75 -0.125,-0.7
  region: -0.325,-0.55 -0.325,-0.7 -0.275,-0.7 -0.275,-0.55
  region: -0.125,-0.7 -0.125,-0.55 -0.275,-0.55 -0.275,-0.7
  region: 0.5,-0.125 0.5,-0.275 0.55,-0.275 0.55,-0.125
  region: 0.7,-0.075 0.55,-0.075 0.55,-0.125 0.7,-0.125
  region: 0.75,-0.275 0.75,-0.125 0.7,-0.125 0.7,-0.275
  rectangle: 0.55,-0.325 0.7,-0.275
  region: 0.7,-0.125 0.55,-0.125 0.55,-0.275 0.7,-0.275
  region: 0.5,0.275 0.5,0.125 0.55,0.125 0.55,0.275
  region: 0.7,0.325 0.55,0.325 0.55,0.275 0.7,0.275
  region: 0.75,0.125 0.75,0.275 0.7,0.275 0.7,0.125
  rectangle: 0.55,0.075 0.7,0.125
  region: 0.7,0.275 0.55,0.275 0.55,0.125 0.7,0.125
  rectangle: 0.125,0.5 0.275,0.55
  region: 0.075,0.7 0.075,0.55 0.125,0.55 0.125,0.7
  region: 0.275,0.75 0.125,0.75 0.125,0.7 0.275,0.7
  region: 0.325,0.55 0.325,0.7 0.275,0.7 0.275,0.55
  region: 0.125,0.7 0.125,0.55 0.275,0.55 0.275,0.7
  rectangle: -0.275,0.5 -0.125,0.55
  region: -0.325,0.7 -0.325,0.55 -0.275,0.55 -0.275,0.7
  region: -0.125,0.75 -0.275,0.75 -0.275,0.7 -0.125,0.7
  region: -0.075,0.55 -0.075,0.7 -0.125,0.7 -0.125,0.55
  region: -0.275,0.7 -0.275,0.55 -0.125,0.55 -0.125,0.7
  rectangle: 0.125,-0.55 0.275,-0.5
  region: 0.125,-0.7 0.125,-0.55 0.075,-0.55 0.075,-0.7
  region: 0.275,-0.7 0.125,-0.7 0.125,-0.75 0.275,-0.75
  region: 0.275,-0.55 0.275,-0.7 0.325,-0.7 0.325,-0.55
  region: 0.275,-0.7 0.275,-0.55 0.125,-0.55 0.125,-0.7
  rectangle: -0.275,0.075 -0.125,0.125
  region: -0.325,0.275 -0.325,0.125 -0.275,0.125 -0.275,0.275
  region: -0.125,0.325 -0.275,0.325 -0.275,0.275 -0.125,0.275
  region: -0.075,0.125 -0.075,0.275 -0.125,0.275 -0.125,0.125
  region: -0.275,0.275 -0.275,0.125 -0.125,0.125 -0.125,0.275
  rectangle: -0.275,-0.325 -0.125,-0.275
  region: -0.325,-0.125 -0.325,-0.275 -0.275,-0.275 -0.275,-0.125
  region: -0.125,-0.075 -0.275,-0.075 -0.275,-0.125 -0.125,-0.125
  region: -0.075,-0.275 -0.075,-0.125 -0.125,-0.125 -0.125,-0.275
  region: -0.275,-0.125 -0.275,-0.275 -0.125,-0.275 -0.125,-0.125
Mechanical 13:
  lines w0.1: -0.81,-0.81 0.81,-0.81 0.81,0.81 -0.81,0.81 -0.81,-0.81
Mechanical 15:
  lines w0.1: -0.5,0 0.5,0 ; 0,-0.5 0,0.5 ; -0.91,-0.91 0.91,-0.91 0.91,0.91 -0.91,0.91 -0.91,-0.91
3D body: height 0.68, standoff 0, extent -0.809,-0.809 0.809,0.809

## SMD40P4X5-1.62X2.02-20V [mm] "Micro SMD, 20-Leads, Body 2.02x1.62mm, Pitch 0.4mm, NSC Recommended"
height 0.68
pads (20):
  round 0.225 smd paste-0.112 mask+0.05: A1(-0.6,0.8) A2(-0.2,0.8) A3(0.2,0.8) A4(0.6,0.8) B1(-0.6,0.4) B2(-0.2,0.4) B3(0.2,0.4) B4(0.6,0.4) C1(-0.6,0) C2(-0.2,0) C3(0.2,0) C4(0.6,0) D1(-0.6,-0.4) D2(-0.2,-0.4) D3(0.2,-0.4) D4(0.6,-0.4) E1(-0.6,-0.8) E2(-0.2,-0.8) E3(0.2,-0.8) E4(0.6,-0.8)
Top Overlay:
  circle w0.1: c-0.925,1.105 r0.05
Top Paste:
  drawing of 180 lines, arcs and shapes, not listed
Mechanical 13:
  lines w0.1: -0.81,-1.01 0.81,-1.01 0.81,1.01 -0.81,1.01 -0.81,-1.01
Mechanical 15:
  lines w0.1: -0.5,0 0.5,0 ; 0,-0.5 0,0.5 ; -0.91,-1.11 0.91,-1.11 0.91,1.11 -0.91,1.11 -0.91,-1.11
3D body: height 0.68, standoff 0, extent -0.809,-1.009 0.809,1.009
